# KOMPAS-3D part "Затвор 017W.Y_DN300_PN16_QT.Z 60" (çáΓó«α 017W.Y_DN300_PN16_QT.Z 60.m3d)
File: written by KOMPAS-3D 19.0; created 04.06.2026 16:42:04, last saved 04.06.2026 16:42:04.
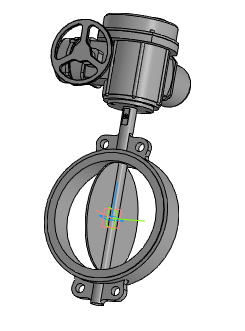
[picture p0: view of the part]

Document properties: Автор: Энергия; Полное имя файла: ..\..\..\3d для проектировщиков\017W разные\x.x Тип 017W.Y(S) Затвор дисковый поворотный межфланцевый\Затвор 017W.Y(S)_DN32-DN450_QT.Z\Затвор 017W.Y_DN300_PN16_QT.Z 60.a3d

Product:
- Part/product: Затвор 017W.Y_DN300_PN16_QT.Z 60
    Масса: 100.258

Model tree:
1. Операция без истории:1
